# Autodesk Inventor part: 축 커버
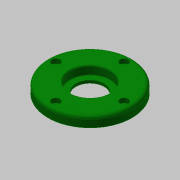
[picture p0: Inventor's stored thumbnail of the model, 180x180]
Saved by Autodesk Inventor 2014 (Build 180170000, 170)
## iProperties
Created: 2015-10
Part Number: 축 커버
Document SubType Name: Modeling
Designer: mdu
Density: 1 g/cm^3
Material: 일반
Appearance: 진녹색
Mass: 42.4472 g
Surface Area: 136.578 cm^2
Volume: 42.4472 cm^3
Author: mdu
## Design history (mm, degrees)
sketch "스케치1"
  geometry: C1 r 40 at (0, 0) reference; C2 r 26 at (0, 0) reference; 1 further point
  node "참조1"
  node "참조2"
extrude "돌출1" new body sketch "스케치1" distance "d0" = 10; taper "d1" = 0 deg
extrude "돌출2" join sketch "스케치1" distance "d2" = 4; taper "d3" = 0 deg
hole "구멍1" diameter "d6" = 27; stored, may be unused: countersink angle "d10" = 90 deg, drill point angle "d12" = 118 deg; dims "d7" = 6, "d8" = 38, "d9" = 8.3, "d11" = 8, "d33" = 10, "d34" = 10
sketch "스케치2"
  geometry: C1 r 20 at (0, 0); 1 further point
  constraints: 1 centre point, 1 coincident
  dimensions: "d13" = 40 diameter of C1
extrude "돌출3" cut sketch "스케치2" distance "d14" = 3; taper "d15" = 0 deg
sketch "스케치3"
  geometry: C1 r 1.621 at (0, 32.5) reference; 1 further point
hole "구멍2" sketch "스케치3" at (0, 32.5) diameter "d16" = 4.5; stored, may be unused: countersink angle "d20" = 90 deg, drill point angle "d22" = 118 deg; dims "d17" = 6, "d18" = 8, "d19" = 4.4, "d21" = 8
fillet "모깎기1" dims "d26" = 3, "d27" = 0.3
chamfer "모따기1" distance "d28" = 1; stored, may be unused: second distance "d29" = 2, angle "d30" = 45 deg
chamfer "모따기2" distance "d31" = 0.8; stored, may be unused: second distance "d32" = 2, angle "d35" = 30 deg
node "솔리드1"
pattern_circular "원형 패턴1" dims angle "d24" = 360 deg
node "참조3"
